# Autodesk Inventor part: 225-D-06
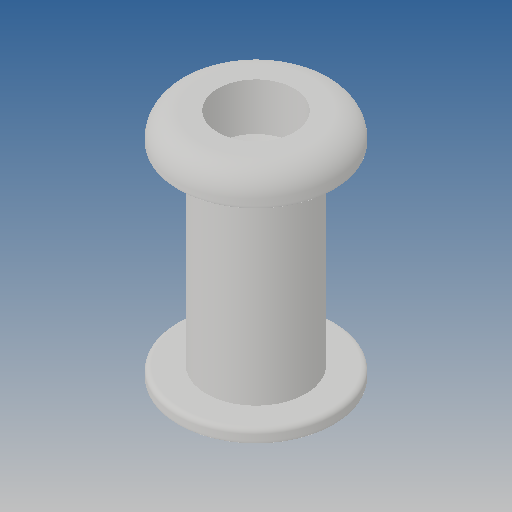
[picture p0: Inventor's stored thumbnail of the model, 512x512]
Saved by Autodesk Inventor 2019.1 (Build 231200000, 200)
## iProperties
Created: 2012-09
Part Number: 225-D-06
Material: Ogólny
Document SubType Name: Modeling
Designer: CADENGINEERING4
Density: 1 g/cm^3
Appearance: Domyślna
Author: CADENGINEERING4
Revision Number: ÈÎºÎ
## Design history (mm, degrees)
feature "Ðý×ª1"
node "Bryła1"
